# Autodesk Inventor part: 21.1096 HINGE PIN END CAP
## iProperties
Created: 2007-01
Part Number: 21.1096 HINGE PIN END CAP
Material: PVC-U
Document SubType Name: Modeling
Designer: Andy Moles
Mass: 0.289627 g
Surface Area: 2.15184 cm^2
Volume: 0.206876 cm^3
Density: 1.4 g/cm^3
Author: Andy Moles
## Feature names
1. Revolution1
